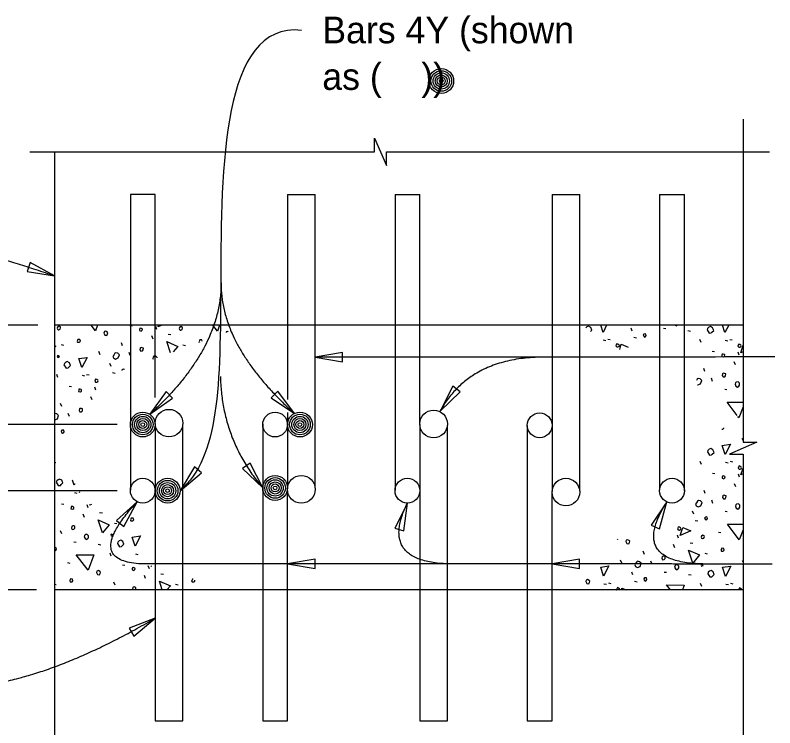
# Model space of a CAD drawing. Extents: x 0 to 34.7, y -1.1 to 13.9.
# Drawn here: x 1.576 to 4.447, y 1.419 to 4.112 of the extents above; entities that cross this region are included whole.
import ezdxf

# ---------------------------------------------------------------- set-up
doc = ezdxf.new("R2010")
doc.units = 0
for name, color, linetype in [('BeamConc', 7, 'Continuous'), ('Miscellaneous', 7, 'Continuous'), ('Rebar', 7, 'Continuous'), ('Rebar_h', 7, 'Continuous'), ('SheetLines_dp', 7, 'Continuous'), ('TextStructures', 7, 'Continuous')]:
    doc.layers.add(name, color=color, linetype=linetype)

msp = doc.modelspace()

# ---------------------------------------------------------------- linework, layer by layer
at = {"layer": 'BeamConc'}
for p, q in [((1.7247, 3.5956), (1.7247, 1.303)), ((4.3264, 2.9397), (1.7247, 2.9397)), ((4.3264, 1.9397), (1.7247, 1.9397))]:
    msp.add_line(p, q, dxfattribs=at)
at = {"layer": 'Miscellaneous'}
for p, q in [((2.0093, 2.9393), (2.0182, 2.9376)), ((2.1107, 2.924), (2.1066, 2.9352)), ((3.908, 2.9178), (3.9039, 2.929)), ((4.0264, 2.929), (4.0347, 2.9279)), ((2.1537, 2.9058), (2.1643, 2.9046)), ((4.1183, 2.9196), (4.1284, 2.9178)), ((1.9816, 2.8621), (1.9769, 2.8739)), ((2.0965, 2.8875), (2.0918, 2.8993)), ((3.7984, 2.8848), (3.8078, 2.8825)), ((3.8155, 2.8878), (3.8249, 2.8854)), ((3.9139, 2.8943), (3.9239, 2.8925)), ((4.1678, 2.8748), (4.1637, 2.886)), ((4.2592, 2.8837), (4.2686, 2.8813)), ((4.2763, 2.8866), (4.2857, 2.8843)), ((1.7489, 2.8675), (1.7583, 2.8651)), ((2.2097, 2.8663), (2.2191, 2.8639)), ((1.8962, 2.8286), (1.8915, 2.8403)), ((2.0105, 2.825), (2.0058, 2.8368)), ((4.2103, 2.8418), (4.2191, 2.8401)), ((4.3116, 2.8265), (4.3075, 2.8377)), ((1.938, 2.7844), (1.9339, 2.7956)), ((4.2975, 2.79), (4.2928, 2.8018)), ((1.9439, 2.7608), (1.9531, 2.7592)), ((4.1826, 2.7646), (4.1779, 2.7764)), ((1.7371, 2.7425), (1.733, 2.7537)), ((1.8284, 2.7514), (1.8379, 2.749)), ((1.8455, 2.7543), (1.8549, 2.752)), ((4.2115, 2.7275), (4.2067, 2.7393)), ((1.7795, 2.7095), (1.7884, 2.7078)), ((1.8809, 2.6942), (1.8767, 2.7054)), ((4.2574, 2.6981), (4.2657, 2.6969)), ((1.7518, 2.6323), (1.7471, 2.6441)), ((1.8667, 2.6577), (1.862, 2.6695)), ((1.7807, 2.5952), (1.776, 2.607)), ((4.3264, 2.5045), (4.3234, 2.5119)), ((1.7247, 2.4223), (1.7292, 2.4211)), ((4.169, 2.414), (4.1649, 2.4252)), ((4.2604, 2.4229), (4.2698, 2.4205)), ((4.2774, 2.4258), (4.2869, 2.4235)), ((4.2115, 2.381), (4.2203, 2.3793)), ((4.3128, 2.3657), (4.3087, 2.3769)), ((4.2987, 2.3292), (4.2939, 2.341)), ((1.7994, 2.3074), (1.8088, 2.3051)), ((1.8164, 2.3104), (1.8206, 2.3093)), ((4.1838, 2.3038), (4.179, 2.3156)), ((4.2126, 2.2667), (4.2079, 2.2785)), ((1.7504, 2.2656), (1.7593, 2.2638)), ((1.8518, 2.2503), (1.8477, 2.2614)), ((1.8377, 2.2137), (1.8329, 2.2255)), ((1.8948, 2.232), (1.9054, 2.2308)), ((4.1402, 2.2261), (4.136, 2.2373)), ((4.2586, 2.2373), (4.2668, 2.2361)), ((1.9508, 2.1925), (1.9602, 2.1901)), ((4.146, 2.2025), (4.1561, 2.2007)), ((1.7516, 2.1513), (1.7469, 2.163)), ((4.2338, 2.1583), (4.2427, 2.1565)), ((4.083, 2.1359), (4.0789, 2.1471)), ((1.7976, 2.1218), (1.8058, 2.1206)), ((1.8895, 2.1124), (1.8995, 2.1106)), ((4.0689, 2.0994), (4.0641, 2.1112)), ((4.126, 2.1176), (4.1366, 2.1165)), ((1.939, 2.0676), (1.9349, 2.0788)), ((2.0303, 2.0764), (2.039, 2.0742)), ((3.9539, 2.074), (3.9492, 2.0858)), ((4.182, 2.0782), (4.1914, 2.0758)), ((1.7728, 2.0428), (1.7817, 2.0411)), ((3.8685, 2.0404), (3.8638, 2.0522)), ((3.9828, 2.0369), (3.9781, 2.0487)), ((4.3264, 2.0466), (4.3246, 2.0511)), ((1.9814, 2.0346), (1.9903, 2.0328)), ((2.0828, 2.0193), (2.0787, 2.0305)), ((2.0686, 1.9827), (2.0639, 1.9945)), ((2.1258, 2.001), (2.1364, 1.9998)), ((3.9103, 1.9963), (3.9062, 2.0074)), ((4.0288, 2.0074), (4.037, 2.0063)), ((4.1207, 1.998), (4.1307, 1.9963)), ((1.7247, 1.9618), (1.7304, 1.9603)), ((1.9537, 1.9574), (1.949, 1.9692)), ((2.1818, 1.9615), (2.1912, 1.9592)), ((3.8007, 1.9633), (3.8102, 1.9609)), ((3.8178, 1.9662), (3.8273, 1.9638)), ((3.9162, 1.9727), (3.9263, 1.9709)), ((4.1702, 1.9532), (4.1661, 1.9644)), ((4.2615, 1.9621), (4.271, 1.9597)), ((4.2786, 1.965), (4.2881, 1.9627))]:
    msp.add_line(p, q, dxfattribs=at)
for points in [[(1.7383, 2.9228), (1.7406, 2.9228), (1.7453, 2.9252), (1.7471, 2.9305), (1.7465, 2.9334), (1.7418, 2.9358), (1.7359, 2.9323), (1.7347, 2.9287), (1.7359, 2.9252), (1.7383, 2.9228)], [(1.8791, 2.9187), (1.8632, 2.9397)], [(1.8869, 2.9397), (1.8791, 2.9187)], [(2.0453, 2.9199), (2.0518, 2.9181), (2.0559, 2.9211), (2.0565, 2.9252), (2.0553, 2.9264), (2.0506, 2.9287), (2.0465, 2.9281), (2.0459, 2.924), (2.0453, 2.9199)], [(2.1166, 2.9334), (2.1185, 2.9397)], [(2.1304, 2.9397), (2.1166, 2.9334)], [(2.1991, 2.9217), (2.2014, 2.9217), (2.2061, 2.924), (2.2079, 2.9293), (2.2073, 2.9323), (2.2026, 2.9346), (2.1967, 2.9311), (2.1955, 2.9276), (2.1967, 2.924), (2.1991, 2.9217)], [(2.3399, 2.9175), (2.3231, 2.9397)], [(2.3482, 2.9397), (2.3399, 2.9175)], [(3.7498, 2.9164), (3.7548, 2.9214), (3.7507, 2.9314), (3.7424, 2.9361), (3.7365, 2.9338), (3.7328, 2.9301)], [(3.7972, 2.9131), (3.7887, 2.9397)], [(3.8109, 2.9397), (3.7972, 2.9131)], [(4.0708, 2.9397), (4.0747, 2.9373), (4.0779, 2.9397)], [(4.1908, 2.9226), (4.1985, 2.9102), (4.2061, 2.9108), (4.2091, 2.9137), (4.2156, 2.9202), (4.2115, 2.9302), (4.2032, 2.9349), (4.1973, 2.9326), (4.1926, 2.9279), (4.1908, 2.9226)], [(4.258, 2.912), (4.2491, 2.9397)], [(4.2723, 2.9397), (4.258, 2.912)], [(1.9121, 2.9081), (1.915, 2.9028), (1.9221, 2.9016), (1.9251, 2.9069), (1.9262, 2.9116), (1.9233, 2.9146), (1.918, 2.9175), (1.9127, 2.9158), (1.9109, 2.9105), (1.9121, 2.9081)], [(2.3809, 2.9152), (2.3788, 2.9164), (2.3735, 2.9146), (2.3727, 2.9121)], [(3.951, 2.8984), (3.9545, 2.8949), (3.9581, 2.8972), (3.9604, 2.9008), (3.9593, 2.9067), (3.9563, 2.9072), (3.9522, 2.9067), (3.9486, 2.9031), (3.951, 2.8984)], [(1.8113, 2.8757), (1.8184, 2.8757), (1.8219, 2.8792), (1.8202, 2.8857), (1.8125, 2.8863), (1.8113, 2.8828), (1.8096, 2.8798), (1.8113, 2.8757), (1.8102, 2.8769)], [(2.1623, 2.8354), (2.1484, 2.8781), (2.1902, 2.8598), (2.1729, 2.8393)], [(2.2824, 2.8792), (2.281, 2.8845), (2.2733, 2.8851), (2.2721, 2.8816), (2.2704, 2.8786), (2.2718, 2.8754)], [(2.2714, 2.8752), (2.271, 2.8757)], [(1.7247, 2.8631), (1.7294, 2.861), (1.7247, 2.8553)], [(2.047, 2.8474), (2.05, 2.8421), (2.0565, 2.8427), (2.0594, 2.8468), (2.06, 2.8533), (2.0559, 2.8551), (2.0529, 2.8557), (2.0494, 2.8545), (2.0482, 2.8533), (2.047, 2.8474)], [(3.8496, 2.8583), (3.8538, 2.8577), (3.8579, 2.8595), (3.8591, 2.863), (3.8573, 2.866), (3.8538, 2.8684), (3.8496, 2.8701), (3.8473, 2.8654), (3.8461, 2.8619), (3.8496, 2.8583)], [(3.8603, 2.8487), (3.8661, 2.8678), (3.8921, 2.8575)], [(4.3104, 2.8572), (4.3146, 2.8566), (4.3187, 2.8583), (4.3199, 2.8619), (4.3181, 2.8648), (4.3146, 2.8672), (4.3104, 2.8689), (4.3081, 2.8642), (4.3069, 2.8607), (4.3104, 2.8572)], [(4.3175, 2.8359), (4.3264, 2.8647)], [(1.7365, 2.8185), (1.743, 2.8215), (1.7406, 2.8238), (1.7365, 2.8256), (1.7347, 2.8215), (1.7365, 2.8185)], [(1.8272, 2.7797), (1.8161, 2.8144), (1.8473, 2.8185), (1.8272, 2.7797)], [(1.9475, 2.8162), (1.9551, 2.8121), (1.9651, 2.8162), (1.9693, 2.8286), (1.9634, 2.8345), (1.9557, 2.8362), (1.9522, 2.8339), (1.948, 2.8274), (1.9451, 2.8221), (1.9475, 2.8162)], [(2.1119, 2.8171), (2.1119, 2.818), (2.1066, 2.8233), (2.1001, 2.8227), (2.0971, 2.8197), (2.0954, 2.8144)], [(2.0954, 2.8144), (2.0968, 2.8116)], [(4.2462, 2.8224), (4.2527, 2.8206), (4.2568, 2.8236), (4.2574, 2.8277), (4.2562, 2.8289), (4.2515, 2.8312), (4.2474, 2.8306), (4.2468, 2.8265), (4.2462, 2.8224)], [(4.3264, 2.8399), (4.3175, 2.8359)], [(1.7601, 2.7903), (1.7677, 2.7779), (1.7754, 2.7785), (1.7783, 2.7814), (1.7848, 2.7879), (1.7807, 2.7979), (1.7724, 2.8026), (1.7666, 2.8003), (1.7618, 2.7956), (1.7601, 2.7903)], [(1.9894, 2.7724), (1.9893, 2.7732), (1.9863, 2.7738), (1.9822, 2.7732), (1.9787, 2.7696), (1.9792, 2.7687)], [(4.248, 2.7499), (4.2509, 2.7446), (4.2574, 2.7452), (4.2604, 2.7493), (4.2609, 2.7558), (4.2568, 2.7576), (4.2539, 2.7582), (4.2503, 2.757), (4.2492, 2.7558), (4.248, 2.7499)], [(1.8797, 2.7249), (1.8838, 2.7243), (1.8879, 2.726), (1.8891, 2.7296), (1.8874, 2.7325), (1.8838, 2.7349), (1.8797, 2.7366), (1.8773, 2.7319), (1.8762, 2.7284), (1.8797, 2.7249)], [(4.1547, 2.7153), (4.1561, 2.7146), (4.1661, 2.7187), (4.1702, 2.7311), (4.1643, 2.7369), (4.1567, 2.7387), (4.1531, 2.7364), (4.1502, 2.7317)], [(1.8155, 2.6901), (1.8219, 2.6883), (1.8261, 2.6913), (1.8267, 2.6954), (1.8255, 2.6966), (1.8208, 2.6989), (1.8166, 2.6983), (1.8161, 2.6942), (1.8155, 2.6901)], [(4.2963, 2.7169), (4.2998, 2.7098), (4.3057, 2.7063), (4.3104, 2.7098), (4.3128, 2.7134), (4.3128, 2.7204), (4.3075, 2.7258), (4.301, 2.7252), (4.2981, 2.7222), (4.2963, 2.7169)], [(4.3046, 2.5987), (4.2663, 2.6491), (4.3264, 2.6486)], [(1.8172, 2.6176), (1.8202, 2.6123), (1.8267, 2.6129), (1.8296, 2.617), (1.8302, 2.6235), (1.8261, 2.6253), (1.8231, 2.6259), (1.8196, 2.6247), (1.8184, 2.6235), (1.8172, 2.6176)], [(4.3264, 2.6312), (4.311, 2.5902)], [(1.7247, 2.5826), (1.7253, 2.5823), (1.7353, 2.5864), (1.7394, 2.5988), (1.7336, 2.6046), (1.7259, 2.6064), (1.7247, 2.6056)], [(4.311, 2.5902), (4.3071, 2.5955)], [(1.7512, 2.5351), (1.7548, 2.5316), (1.7583, 2.5339), (1.7607, 2.5375), (1.7595, 2.5434), (1.7565, 2.544), (1.7524, 2.5434), (1.7489, 2.5398), (1.7512, 2.5351)], [(4.2468, 2.5472), (4.2503, 2.5472), (4.2539, 2.5507), (4.2534, 2.5525)], [(4.192, 2.4618), (4.1997, 2.4494), (4.2073, 2.45), (4.2103, 2.4529), (4.2168, 2.4594), (4.2126, 2.4694), (4.2044, 2.4741), (4.1985, 2.4718), (4.1938, 2.4671), (4.192, 2.4618)], [(4.2592, 2.4512), (4.248, 2.4859), (4.2792, 2.49), (4.2592, 2.4512)], [(4.3116, 2.3964), (4.3158, 2.3958), (4.3199, 2.3975), (4.3211, 2.4011), (4.3193, 2.404), (4.3158, 2.4064), (4.3116, 2.4081), (4.3093, 2.4034), (4.3081, 2.3999), (4.3116, 2.3964)], [(4.3187, 2.3751), (4.3264, 2.4)], [(1.731, 2.3463), (1.7387, 2.3339), (1.7463, 2.3345), (1.7493, 2.3375), (1.7558, 2.3439), (1.7516, 2.354), (1.7434, 2.3587), (1.7375, 2.3563), (1.7328, 2.3516), (1.731, 2.3463)], [(1.7982, 2.3357), (1.7921, 2.3545)], [(4.2474, 2.3616), (4.2539, 2.3598), (4.258, 2.3628), (4.2586, 2.3669), (4.2574, 2.3681), (4.2527, 2.3704), (4.2486, 2.3698), (4.248, 2.3657), (4.2474, 2.3616)], [(4.3264, 2.3786), (4.3187, 2.3751)], [(1.8008, 2.3408), (1.7982, 2.3357)], [(4.2492, 2.2891), (4.2521, 2.2838), (4.2586, 2.2844), (4.2615, 2.2885), (4.2621, 2.295), (4.258, 2.2968), (4.2551, 2.2974), (4.2515, 2.2962), (4.2503, 2.295), (4.2492, 2.2891)], [(4.1496, 2.2579), (4.1572, 2.2538), (4.1673, 2.2579), (4.1714, 2.2703), (4.1655, 2.2761), (4.1578, 2.2779), (4.1543, 2.2756), (4.1502, 2.2691), (4.1472, 2.2638), (4.1496, 2.2579)], [(1.7864, 2.2461), (1.7929, 2.2444), (1.797, 2.2473), (1.7976, 2.2514), (1.7964, 2.2526), (1.7917, 2.255), (1.7876, 2.2544), (1.787, 2.2503), (1.7864, 2.2461)], [(1.8577, 2.2597), (1.8589, 2.2636)], [(1.8641, 2.2626), (1.8577, 2.2597)], [(4.2975, 2.2561), (4.301, 2.249), (4.3069, 2.2455), (4.3116, 2.249), (4.314, 2.2526), (4.314, 2.2596), (4.3087, 2.265), (4.3022, 2.2644), (4.2993, 2.2614), (4.2975, 2.2561)], [(2.0133, 2.2008), (2.0203, 2.2008), (2.0239, 2.2043), (2.0221, 2.2108), (2.0144, 2.2114), (2.0133, 2.2078), (2.0115, 2.2049), (2.0133, 2.2008), (2.0121, 2.2019)], [(4.1832, 2.2066), (4.1867, 2.2031), (4.1902, 2.2054), (4.1926, 2.209), (4.1914, 2.2149), (4.1885, 2.2155), (4.1843, 2.2149), (4.1808, 2.2113), (4.1832, 2.2066)], [(1.7882, 2.1736), (1.7911, 2.1683), (1.7976, 2.1689), (1.8005, 2.1731), (1.8011, 2.1795), (1.797, 2.1813), (1.7941, 2.1819), (1.7905, 2.1807), (1.7893, 2.1795), (1.7882, 2.1736)], [(1.9054, 2.1554), (1.8895, 2.2043), (1.9313, 2.186), (1.9054, 2.1554)], [(4.3122, 2.1294), (4.2674, 2.1883), (4.3264, 2.1878)], [(4.0818, 2.1665), (4.0859, 2.166), (4.0901, 2.1677), (4.0912, 2.1713), (4.0895, 2.1742), (4.0859, 2.1766), (4.0818, 2.1783), (4.0795, 2.1736), (4.0783, 2.1701), (4.0818, 2.1665)], [(4.0889, 2.1453), (4.0983, 2.176), (4.1295, 2.1636), (4.0889, 2.1453)], [(4.3264, 2.1673), (4.3122, 2.1294)], [(1.8365, 2.1406), (1.84, 2.1336), (1.8459, 2.13), (1.8506, 2.1336), (1.853, 2.1371), (1.853, 2.1442), (1.8477, 2.1495), (1.8412, 2.1489), (1.8382, 2.146), (1.8365, 2.1406)], [(1.9384, 2.1436), (1.9449, 2.1465), (1.9425, 2.1489), (1.9384, 2.1507), (1.9367, 2.1465), (1.9384, 2.1436)], [(1.962, 2.1153), (1.9697, 2.1029), (1.9773, 2.1035), (1.9803, 2.1065), (1.9867, 2.113), (1.9826, 2.123), (1.9744, 2.1277), (1.9685, 2.1253), (1.9638, 2.1206), (1.962, 2.1153)], [(2.0292, 2.1047), (2.018, 2.1395), (2.0492, 2.1436), (2.0292, 2.1047)], [(3.8514, 2.1306), (3.8509, 2.1313)], [(3.8517, 2.1313), (3.8514, 2.1306)], [(3.8844, 2.12), (3.8874, 2.1147), (3.8944, 2.1135), (3.8974, 2.1188), (3.8986, 2.1235), (3.8956, 2.1265), (3.8903, 2.1294), (3.885, 2.1277), (3.8832, 2.1224), (3.8844, 2.12)], [(4.1714, 2.1335), (4.1737, 2.1335), (4.1785, 2.1359), (4.1802, 2.1412), (4.1796, 2.1442), (4.1749, 2.1465), (4.169, 2.143), (4.1678, 2.1394), (4.169, 2.1359), (4.1714, 2.1335)], [(1.7247, 2.0887), (1.7257, 2.0876), (1.7292, 2.09), (1.7316, 2.0935), (1.7304, 2.0994), (1.7275, 2.1), (1.7247, 2.0996)], [(4.2445, 2.0864), (4.2515, 2.0864), (4.2551, 2.0899), (4.2533, 2.0964), (4.2456, 2.097), (4.2445, 2.0935), (4.2427, 2.0905), (4.2445, 2.0864), (4.2433, 2.0876)], [(1.8512, 2.014), (1.8064, 2.0729), (1.873, 2.0723), (1.8512, 2.014)], [(4.0194, 2.0593), (4.0223, 2.054), (4.0288, 2.0546), (4.0317, 2.0587), (4.0323, 2.0652), (4.0282, 2.067), (4.0252, 2.0676), (4.0217, 2.0664), (4.0205, 2.0652), (4.0194, 2.0593)], [(4.1366, 2.041), (4.1207, 2.0899), (4.1625, 2.0717), (4.1366, 2.041)], [(3.9198, 2.0281), (3.9274, 2.0239), (3.9374, 2.0281), (3.9416, 2.0404), (3.9357, 2.0463), (3.928, 2.0481), (3.9245, 2.0457), (3.9204, 2.0393), (3.9174, 2.034), (3.9198, 2.0281)], [(1.8842, 2.0034), (1.8872, 1.998), (1.8942, 1.9969), (1.8972, 2.0022), (1.8984, 2.0069), (1.8954, 2.0098), (1.8901, 2.0128), (1.8848, 2.011), (1.883, 2.0057), (1.8842, 2.0034)], [(2.0174, 2.0151), (2.0239, 2.0134), (2.028, 2.0163), (2.0286, 2.0204), (2.0274, 2.0216), (2.0227, 2.024), (2.0186, 2.0234), (2.018, 2.0193), (2.0174, 2.0151)], [(2.0887, 2.0287), (2.089, 2.0296)], [(2.0902, 2.0294), (2.0887, 2.0287)], [(3.7996, 1.9915), (3.7884, 2.0263), (3.8196, 2.0304), (3.7996, 1.9915)], [(4.0677, 2.0263), (4.0712, 2.0192), (4.0771, 2.0157), (4.0818, 2.0192), (4.0842, 2.0228), (4.0842, 2.0298), (4.0789, 2.0351), (4.0724, 2.0346), (4.0694, 2.0316), (4.0677, 2.0263)], [(4.1696, 2.0293), (4.1761, 2.0322), (4.1737, 2.0346), (4.1696, 2.0363), (4.1678, 2.0322), (4.1696, 2.0293)], [(4.1932, 2.001), (4.2008, 1.9886), (4.2085, 1.9892), (4.2115, 1.9921), (4.2179, 1.9986), (4.2138, 2.0086), (4.2056, 2.0133), (4.1997, 2.011), (4.195, 2.0063), (4.1932, 2.001)], [(4.2604, 1.9904), (4.2492, 2.0251), (4.2804, 2.0293), (4.2604, 1.9904)], [(1.7834, 1.9709), (1.7905, 1.9709), (1.7941, 1.9745), (1.7923, 1.981), (1.7846, 1.9816), (1.7834, 1.978), (1.7817, 1.9751), (1.7834, 1.9709), (1.7823, 1.9721)], [(3.9534, 1.9768), (3.9569, 1.9733), (3.9604, 1.9756), (3.9628, 1.9792), (3.9616, 1.9851), (3.9587, 1.9856), (3.9545, 1.9851), (3.951, 1.9815), (3.9534, 1.9768)], [(2.1314, 1.9397), (2.1205, 1.9733), (2.1623, 1.955), (2.1493, 1.9397)], [(2.2484, 1.9801), (2.2454, 1.9804), (2.2442, 1.9768), (2.2425, 1.9739), (2.2442, 1.9698), (2.2431, 1.9709)], [(2.2442, 1.9698), (2.2513, 1.9698), (2.2549, 1.9733), (2.254, 1.9765)], [(3.7331, 1.9691), (3.7361, 1.9638), (3.7431, 1.9626), (3.7461, 1.9679), (3.7473, 1.9726), (3.7443, 1.9756), (3.739, 1.9785), (3.7337, 1.9768), (3.7319, 1.9715), (3.7331, 1.9691)], [(4.052, 1.9397), (4.0376, 1.9585), (4.1042, 1.958), (4.0974, 1.9397)], [(2.0298, 1.9397), (2.0315, 1.9421), (2.0321, 1.9486), (2.028, 1.9503), (2.025, 1.9509), (2.0215, 1.9497), (2.0203, 1.9486), (2.0191, 1.9427)], [(2.0191, 1.9427), (2.0208, 1.9397)], [(3.8608, 1.9397), (3.8614, 1.9415), (3.8597, 1.9444), (3.8561, 1.9468), (3.852, 1.9485), (3.8496, 1.9438), (3.8485, 1.9403), (3.8491, 1.9397)], [(3.8665, 1.9397), (3.8685, 1.9462), (3.8849, 1.9397)], [(4.322, 1.9397), (4.3222, 1.9403), (4.3205, 1.9432), (4.3169, 1.9456), (4.3128, 1.9473), (4.3104, 1.9426), (4.3095, 1.9397)]]:
    msp.add_lwpolyline(points, dxfattribs=at)
at = {"layer": 'Rebar'}
for centre, radius in [((3.1859, 3.8629), 0.0469), ((3.1859, 3.8629), 0.0389), ((3.1859, 3.8629), 0.0309), ((3.1859, 3.8629), 0.0229), ((3.1859, 3.8629), 0.0149), ((3.1859, 3.8629), 0.0069), ((2.1569, 2.5699), 0.0521), ((3.157, 2.5668), 0.0521), ((2.0579, 2.5647), 0.0469), ((2.0579, 2.5647), 0.0389), ((2.0579, 2.5647), 0.0309), ((2.0579, 2.5647), 0.0229), ((2.558, 2.5647), 0.0469), ((2.6518, 2.5647), 0.0469), ((2.6518, 2.5647), 0.0389), ((2.6518, 2.5647), 0.0309), ((2.6518, 2.5647), 0.0229), ((3.558, 2.5616), 0.0469), ((2.0579, 2.5647), 0.0149), ((2.0579, 2.5647), 0.0069), ((2.6518, 2.5647), 0.0149), ((2.6518, 2.5647), 0.0069), ((2.058, 2.3147), 0.0469), ((2.1517, 2.3147), 0.0469), ((2.558, 2.3251), 0.0469), ((2.558, 2.3251), 0.0389), ((2.558, 2.3251), 0.0309), ((2.657, 2.3199), 0.0521), ((3.058, 2.3147), 0.0469), ((3.657, 2.3095), 0.0521), ((4.058, 2.3147), 0.0469), ((2.1517, 2.3147), 0.0389), ((2.1517, 2.3147), 0.0309), ((2.1517, 2.3147), 0.0229), ((2.1517, 2.3147), 0.0149), ((2.558, 2.3251), 0.0229), ((2.558, 2.3251), 0.0149), ((2.558, 2.3251), 0.0069), ((2.1517, 2.3147), 0.0069)]:
    msp.add_circle(centre, radius, dxfattribs=at)
at = {"layer": 'Rebar_h'}
for p, q in [((2.1049, 3.4344), (2.0111, 3.4344)), ((2.6049, 3.4344), (2.7091, 3.4344)), ((3.0111, 3.4344), (3.1049, 3.4344)), ((3.6049, 3.4344), (3.7091, 3.4344)), ((4.0111, 3.4344), (4.1049, 3.4344)), ((2.1048, 1.4449), (2.209, 1.4449)), ((2.5111, 1.4449), (2.6049, 1.4449)), ((3.1048, 1.4449), (3.2091, 1.4449)), ((3.5111, 1.4449), (3.6049, 1.4449))]:
    msp.add_line(p, q, dxfattribs=at)
for points in [[(2.0111, 3.4344), (2.0111, 2.3168)], [(2.1049, 2.6667), (2.1049, 3.4344)], [(2.6049, 3.4344), (2.6049, 2.6598)], [(2.7091, 2.3251), (2.7091, 3.4344)], [(3.0111, 3.4344), (3.0111, 2.3168)], [(3.1049, 2.5647), (3.1049, 3.4344)], [(3.6049, 3.4344), (3.6049, 2.3116)], [(3.7091, 2.3147), (3.7091, 3.4344)], [(4.0111, 3.4344), (4.0111, 2.3168)], [(4.1049, 2.3147), (4.1049, 3.4344)], [(2.6049, 2.6108), (2.6049, 2.323)], [(2.1048, 2.5594), (2.1048, 1.4449)], [(2.209, 1.4449), (2.209, 2.5647)], [(2.5111, 2.5668), (2.5111, 1.4449)], [(3.1048, 2.5647), (3.1048, 1.4449)], [(3.2091, 1.4449), (3.2091, 2.5595)], [(3.5111, 2.5616), (3.5111, 1.4449)], [(2.6049, 1.4449), (2.6049, 2.3147)], [(3.6049, 1.4449), (3.6049, 2.3116)]]:
    msp.add_lwpolyline(points, dxfattribs=at)
at = {"layer": 'SheetLines_dp'}
for p, q in [((1.6613, 2.9397), (0.9569, 2.9397)), ((1.9607, 2.5647), (0.9751, 2.5647)), ((1.9607, 2.3147), (0.9751, 2.3147)), ((1.6557, 1.9397), (0.4975, 1.9397))]:
    msp.add_line(p, q, dxfattribs=at)
for points in [[(4.3264, 3.7184), (4.3264, 2.498), (4.378, 2.498), (4.3264, 2.4755), (4.2747, 2.453), (4.3264, 2.453), (4.3264, 1.1884)], [(1.6316, 3.5956), (2.934, 3.5956), (2.934, 3.6473), (2.9565, 3.5956), (2.979, 3.5439), (2.979, 3.5956), (4.4262, 3.5956)]]:
    msp.add_lwpolyline(points, dxfattribs=at)
for points in [[(1.7247, 3.1267), (1.6318, 3.177), (1.6204, 3.1436)], [(2.7088, 2.8192), (2.8129, 2.8015), (2.8129, 2.8368)], [(3.1816, 2.6156), (3.258, 2.6886), (3.2297, 2.7097)], [(2.0846, 2.6033), (2.1708, 2.6642), (2.1459, 2.6892)], [(2.6311, 2.6067), (2.5679, 2.6914), (2.5436, 2.6659)], [(2.5111, 2.3251), (2.4635, 2.4193), (2.4351, 2.3983)], [(2.1986, 2.3147), (2.2799, 2.3822), (2.2531, 2.4052)], [(2.0367, 2.2728), (1.9586, 2.2016), (1.9864, 2.1799)], [(4.0385, 2.272), (3.979, 2.1847), (4.0111, 2.17)], [(3.058, 2.2678), (3.0109, 2.1732), (3.0447, 2.163)], [(2.6049, 2.0379), (2.709, 2.0203), (2.709, 2.0556)], [(3.6049, 2.0379), (3.709, 2.0203), (3.709, 2.0556)], [(2.1048, 1.8331), (2.006, 1.7958), (2.0238, 1.7654)]]:
    msp.add_lwpolyline(points, close=True, dxfattribs=at)
for points, degree in [([(2.6578, 4.0543), (2.3543, 4.0877), (2.3544, 2.9627), (2.3473, 2.4447), (2.1986, 2.3147)], 3), ([(1.07, 3.2736), (1.2943, 3.2736), (1.7247, 3.1267)], 2), ([(2.3538, 3.1002), (2.3545, 2.8499), (2.0846, 2.6033)], 2), ([(2.3538, 3.1002), (2.3519, 2.8577), (2.6311, 2.6067)], 2), ([(4.4465, 2.8207), (4.2105, 2.8192), (3.7573, 2.8192), (2.7088, 2.8192)], 3), ([(3.5781, 2.8192), (3.296, 2.8206), (3.1816, 2.6156)], 2), ([(2.3514, 2.7456), (2.3564, 2.5072), (2.5111, 2.3251)], 2), ([(4.4364, 2.0372), (3.9532, 2.0379), (3.541, 2.0379), (2.3287, 2.0379), (1.8202, 2.0379), (2.0367, 2.2728)], 2), ([(4.1938, 2.0375), (3.888, 2.0372), (4.0385, 2.272)], 2), ([(3.2204, 2.0379), (2.9476, 2.0432), (3.058, 2.2678)], 2), ([(1.3437, 1.5719), (1.6577, 1.5719), (2.1048, 1.8331)], 2)]:
    msp.add_open_spline(points, degree=degree, dxfattribs=at)

# ---------------------------------------------------------------- texts
at = {"layer": 'TextStructures'}
for s, p in [('Bars 4Y (shown', (2.7363, 4.0053)), ('as (    ))', (2.7363, 3.8293))]:
    msp.add_text(s, height=0.1008, dxfattribs=at).set_placement(p)

doc.saveas('drawing.dxf')
